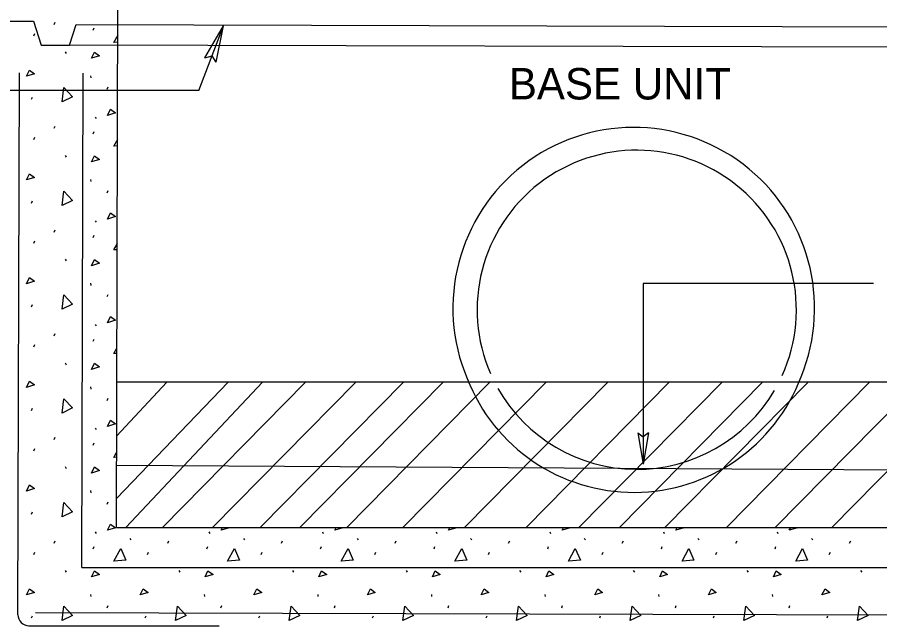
# Model space of a CAD drawing. Extents: x 4.74 to 11.91, y -5.26 to 4.54.
# Drawn here: x 6.154 to 7.798, y -1.238 to -0.077 of the extents above; entities that cross this region are included whole.
import ezdxf

# ---------------------------------------------------------------- set-up
doc = ezdxf.new("R2010")
doc.units = 0
for name, color, linetype in [('DETL-DIMS', 7, 'Continuous'), ('DETL-LINE', 7, 'Continuous'), ('DETL-NOTE', 7, 'Continuous'), ('DETL-PATT', 7, 'Continuous')]:
    doc.layers.add(name, color=color, linetype=linetype)

msp = doc.modelspace()

# ---------------------------------------------------------------- linework, layer by layer
at = {"layer": 'DETL-DIMS'}
for p, q in [((6.4998, -0.2168), (6.5467, -0.0933)), ((6.511, -0.1546), (6.5467, -0.0933)), ((6.5328, -0.1629), (6.5467, -0.0933)), ((6.511, -0.1546), (6.525, -0.1506)), ((6.5328, -0.1629), (6.525, -0.1506)), ((6.4998, -0.2168), (5.9955, -0.2168)), ((7.7863, -0.5848), (7.3468, -0.5848)), ((7.3468, -0.5848), (7.3468, -0.9299)), ((7.3368, -0.8699), (7.3468, -0.9299)), ((7.3368, -0.8699), (7.3468, -0.8774)), ((7.3568, -0.8699), (7.3468, -0.9299)), ((7.3568, -0.8699), (7.3468, -0.8774))]:
    msp.add_line(p, q, dxfattribs=at)
at = {"layer": 'DETL-LINE'}
for p, q in [((6.3425, -1.0502), (6.3468, 0.546)), ((6.1042, -0.0844), (6.1844, -0.0846)), ((6.1844, -0.0846), (6.1993, -0.1302)), ((6.253, -0.1303), (6.2659, -0.0908)), ((6.2659, -0.0908), (8.4204, -0.0965)), ((6.1993, -0.1302), (6.253, -0.1303)), ((6.253, -0.1293), (8.4421, -0.1351)), ((6.1549, -1.217), (6.1576, -0.1831)), ((6.2769, -1.1267), (6.2794, -0.1834)), ((8.3579, -0.7729), (6.3432, -0.7729)), ((6.3428, -0.9314), (8.3574, -0.9435)), ((6.3425, -1.0502), (8.3571, -1.0502)), ((6.2769, -1.1267), (8.425, -1.1267)), ((6.1881, -1.2125), (8.5207, -1.2187)), ((6.1757, -1.238), (6.5385, -1.238))]:
    msp.add_line(p, q, dxfattribs=at)
for centre, radius, start, end in [((7.329, -0.632), 0.3448, 337.6753, 202.9248), ((7.3347, -0.635), 0.3044, 335.6094, 203.5958), ((7.3291, -0.6425), 0.3409, 201.2948, 339.3052), ((7.3347, -0.635), 0.3044, 209.5167, 329.5671), ((6.1757, -1.2171), 0.0208, 179.7589, 270)]:
    msp.add_arc(centre, radius, start, end, dxfattribs=at)
at = {"layer": 'DETL-PATT'}
for p, q in [((6.2238, -0.0909), (6.226, -0.0866)), ((6.2984, -0.1014), (6.3, -0.0972)), ((6.1852, -0.1122), (6.1873, -0.1079)), ((6.2448, -0.1428), (6.2469, -0.146)), ((6.2931, -0.1884), (6.2936, -0.1927)), ((6.3251, -0.2142), (6.3267, -0.2099)), ((6.1809, -0.2335), (6.1825, -0.2292)), ((6.3022, -0.2673), (6.3038, -0.27)), ((6.2238, -0.2888), (6.226, -0.2845)), ((6.2984, -0.2994), (6.3, -0.2951)), ((6.1852, -0.3101), (6.1873, -0.3058)), ((6.2448, -0.3407), (6.2469, -0.3439)), ((6.2931, -0.3863), (6.2936, -0.3906)), ((6.3251, -0.4121), (6.3267, -0.4078)), ((6.1809, -0.4314), (6.1825, -0.4271)), ((6.3022, -0.4652), (6.3038, -0.4679)), ((6.2238, -0.4867), (6.226, -0.4824)), ((6.2984, -0.4973), (6.3, -0.493)), ((6.1852, -0.508), (6.1873, -0.5037)), ((6.2448, -0.5386), (6.2469, -0.5418)), ((6.2931, -0.5842), (6.2936, -0.5885)), ((6.3251, -0.61), (6.3267, -0.6057)), ((6.1809, -0.6293), (6.1825, -0.625)), ((6.3022, -0.6631), (6.3038, -0.6658)), ((6.2238, -0.6846), (6.226, -0.6803)), ((6.1852, -0.7059), (6.1873, -0.7016)), ((6.2984, -0.6952), (6.3, -0.6909)), ((6.2448, -0.7365), (6.2469, -0.7398)), ((6.3427, -0.995), (6.5556, -0.7729)), ((6.343, -0.8765), (6.4388, -0.7729)), ((6.3606, -1.0502), (6.621, -0.7729)), ((6.4303, -1.0502), (6.7033, -0.7729)), ((6.5258, -1.0502), (6.7988, -0.7729)), ((6.617, -1.0502), (6.8901, -0.7729)), ((6.6926, -1.0502), (6.9656, -0.7729)), ((6.7817, -1.0502), (7.0547, -0.7729)), ((6.8889, -1.0502), (7.162, -0.7729)), ((7.0066, -1.0502), (7.2797, -0.7729)), ((7.1237, -1.0502), (7.3968, -0.7729)), ((7.2243, -1.0502), (7.4974, -0.7729)), ((7.3017, -1.0502), (7.5747, -0.7729)), ((7.3885, -1.0502), (7.6615, -0.7729)), ((7.5056, -1.0502), (7.7787, -0.7729)), ((7.5988, -1.0502), (7.8718, -0.7729)), ((7.7064, -1.0502), (7.9795, -0.7729)), ((6.2931, -0.7822), (6.2936, -0.7864)), ((6.3251, -0.8079), (6.3267, -0.8036)), ((6.1809, -0.8272), (6.1825, -0.8229)), ((6.3022, -0.8611), (6.3038, -0.8637)), ((6.2238, -0.8825), (6.226, -0.8782)), ((6.1852, -0.9039), (6.1873, -0.8996)), ((6.2984, -0.8931), (6.3, -0.8888)), ((6.2448, -0.9344), (6.2469, -0.9377)), ((6.2931, -0.9801), (6.2936, -0.9844)), ((6.3251, -1.0058), (6.3267, -1.0015)), ((6.1809, -1.0252), (6.1825, -1.0209)), ((6.3022, -1.059), (6.3038, -1.0617)), ((6.5189, -1.059), (6.5205, -1.0617)), ((6.7355, -1.059), (6.7371, -1.0617)), ((6.9522, -1.059), (6.9538, -1.0617)), ((7.1689, -1.059), (7.1705, -1.0617)), ((7.3855, -1.059), (7.3871, -1.0617)), ((7.6022, -1.059), (7.6038, -1.0617)), ((6.2238, -1.0804), (6.226, -1.0762)), ((6.368, -1.0713), (6.3702, -1.074)), ((6.4405, -1.0804), (6.4426, -1.0762)), ((6.5847, -1.0713), (6.5868, -1.074)), ((6.6572, -1.0804), (6.6593, -1.0762)), ((6.8014, -1.0713), (6.8035, -1.074)), ((6.8738, -1.0804), (6.876, -1.0762)), ((7.018, -1.0713), (7.0202, -1.074)), ((7.0905, -1.0804), (7.0926, -1.0762)), ((7.2347, -1.0713), (7.2368, -1.074)), ((7.3072, -1.0804), (7.3093, -1.0762)), ((7.4514, -1.0713), (7.4535, -1.074)), ((7.5238, -1.0804), (7.526, -1.0762)), ((7.668, -1.0713), (7.6702, -1.074)), ((7.7405, -1.0804), (7.7426, -1.0762)), ((6.1852, -1.1018), (6.1873, -1.0975)), ((6.2984, -1.091), (6.3, -1.0867)), ((6.4018, -1.1018), (6.404, -1.0975)), ((6.5151, -1.091), (6.5167, -1.0867)), ((6.6185, -1.1018), (6.6207, -1.0975)), ((6.7318, -1.091), (6.7334, -1.0867)), ((6.8352, -1.1018), (6.8373, -1.0975)), ((6.9484, -1.091), (6.95, -1.0867)), ((7.0518, -1.1018), (7.054, -1.0975)), ((7.1651, -1.091), (7.1667, -1.0867)), ((7.2685, -1.1018), (7.2707, -1.0975)), ((7.3818, -1.091), (7.3834, -1.0867)), ((7.4852, -1.1018), (7.4873, -1.0975)), ((7.5984, -1.091), (7.6, -1.0867)), ((7.7018, -1.1018), (7.704, -1.0975)), ((6.2448, -1.1324), (6.2469, -1.1356)), ((6.4614, -1.1324), (6.4636, -1.1356)), ((6.6781, -1.1324), (6.6802, -1.1356)), ((6.8948, -1.1324), (6.8969, -1.1356)), ((7.1114, -1.1324), (7.1136, -1.1356)), ((7.3281, -1.1324), (7.3302, -1.1356)), ((7.5448, -1.1324), (7.5469, -1.1356)), ((7.7614, -1.1324), (7.7636, -1.1356)), ((6.2931, -1.178), (6.2936, -1.1823)), ((6.5097, -1.178), (6.5103, -1.1823)), ((6.7264, -1.178), (6.7269, -1.1823)), ((6.9431, -1.178), (6.9436, -1.1823)), ((7.1597, -1.178), (7.1603, -1.1823)), ((7.3764, -1.178), (7.3769, -1.1823)), ((7.5931, -1.178), (7.5936, -1.1823)), ((6.3251, -1.2038), (6.3267, -1.1995)), ((6.5418, -1.2038), (6.5434, -1.1995)), ((6.7584, -1.2038), (6.76, -1.1995)), ((6.9751, -1.2038), (6.9767, -1.1995)), ((7.1918, -1.2038), (7.1934, -1.1995)), ((7.4084, -1.2038), (7.41, -1.1995)), ((7.6251, -1.2038), (7.6267, -1.1995)), ((6.1809, -1.2231), (6.1825, -1.2188)), ((6.3975, -1.2231), (6.3992, -1.2188)), ((6.6142, -1.2231), (6.6158, -1.2188)), ((6.8309, -1.2231), (6.8325, -1.2188)), ((7.0475, -1.2231), (7.0492, -1.2188)), ((7.2642, -1.2231), (7.2658, -1.2188)), ((7.4809, -1.2231), (7.4825, -1.2188)), ((7.6975, -1.2231), (7.6992, -1.2188))]:
    msp.add_line(p, q, dxfattribs=at)
for points in [[(6.338, -0.1251), (6.3459, -0.1102)], [(6.3458, -0.1245), (6.338, -0.1251)], [(6.2952, -0.1551), (6.3006, -0.1433), (6.3102, -0.1503), (6.2952, -0.1551)], [(6.1712, -0.1895), (6.1771, -0.1777), (6.1862, -0.1846), (6.1712, -0.1895)], [(6.2389, -0.2383), (6.2426, -0.2109), (6.2592, -0.2287), (6.2389, -0.2383)], [(6.3256, -0.2641), (6.3315, -0.2523), (6.3412, -0.2593), (6.3256, -0.2641)], [(6.338, -0.323), (6.3452, -0.3095)], [(6.3451, -0.3225), (6.338, -0.323)], [(6.2952, -0.353), (6.3006, -0.3412), (6.3102, -0.3482), (6.2952, -0.353)], [(6.1712, -0.3874), (6.1771, -0.3756), (6.1862, -0.3826), (6.1712, -0.3874)], [(6.2389, -0.4362), (6.2426, -0.4089), (6.2592, -0.4266), (6.2389, -0.4362)], [(6.3256, -0.462), (6.3315, -0.4502), (6.3412, -0.4572), (6.3256, -0.462)], [(6.338, -0.5209), (6.3445, -0.5087)], [(6.3444, -0.5204), (6.338, -0.5209)], [(6.2952, -0.551), (6.3006, -0.5391), (6.3102, -0.5461), (6.2952, -0.551)], [(6.1712, -0.5853), (6.1771, -0.5735), (6.1862, -0.5805), (6.1712, -0.5853)], [(6.2389, -0.6342), (6.2426, -0.6068), (6.2592, -0.6245), (6.2389, -0.6342)], [(6.3256, -0.6599), (6.3315, -0.6481), (6.3412, -0.6551), (6.3256, -0.6599)], [(6.338, -0.7188), (6.3437, -0.708)], [(6.3437, -0.7184), (6.338, -0.7188)], [(6.2952, -0.7489), (6.3006, -0.7371), (6.3102, -0.744), (6.2952, -0.7489)], [(6.1712, -0.7832), (6.1771, -0.7714), (6.1862, -0.7784), (6.1712, -0.7832)], [(6.2389, -0.8321), (6.2426, -0.8047), (6.2592, -0.8224), (6.2389, -0.8321)], [(6.3256, -0.8578), (6.3315, -0.846), (6.3412, -0.853), (6.3256, -0.8578)], [(6.338, -0.9167), (6.343, -0.9073)], [(6.343, -0.9164), (6.338, -0.9167)], [(6.2952, -0.9468), (6.3006, -0.935), (6.3102, -0.942), (6.2952, -0.9468)], [(6.1712, -0.9811), (6.1771, -0.9693), (6.1862, -0.9763), (6.1712, -0.9811)], [(6.2389, -1.03), (6.2426, -1.0026), (6.2592, -1.0203), (6.2389, -1.03)], [(6.3256, -1.0558), (6.3315, -1.0439), (6.3412, -1.0509), (6.3256, -1.0558)], [(6.5423, -1.0558), (6.5451, -1.0502)], [(6.5569, -1.0502), (6.5579, -1.0509), (6.5423, -1.0558)], [(6.759, -1.0558), (6.7617, -1.0502)], [(6.7735, -1.0502), (6.7745, -1.0509), (6.759, -1.0558)], [(6.9756, -1.0558), (6.9784, -1.0502)], [(6.9902, -1.0502), (6.9912, -1.0509), (6.9756, -1.0558)], [(7.1923, -1.0558), (7.1951, -1.0502)], [(7.2069, -1.0502), (7.2079, -1.0509), (7.1923, -1.0558)], [(7.409, -1.0558), (7.4117, -1.0502)], [(7.4235, -1.0502), (7.4245, -1.0509), (7.409, -1.0558)], [(7.6256, -1.0558), (7.6284, -1.0502)], [(7.6402, -1.0502), (7.6412, -1.0509), (7.6256, -1.0558)], [(6.338, -1.1146), (6.3509, -1.0905), (6.3605, -1.113), (6.338, -1.1146)], [(6.5546, -1.1146), (6.5675, -1.0905), (6.5772, -1.113), (6.5546, -1.1146)], [(6.7713, -1.1146), (6.7842, -1.0905), (6.7938, -1.113), (6.7713, -1.1146)], [(6.988, -1.1146), (7.0009, -1.0905), (7.0105, -1.113), (6.988, -1.1146)], [(7.2046, -1.1146), (7.2175, -1.0905), (7.2272, -1.113), (7.2046, -1.1146)], [(7.4213, -1.1146), (7.4342, -1.0905), (7.4438, -1.113), (7.4213, -1.1146)], [(7.638, -1.1146), (7.6509, -1.0905), (7.6605, -1.113), (7.638, -1.1146)], [(6.2952, -1.1447), (6.3006, -1.1329), (6.3102, -1.1399), (6.2952, -1.1447)], [(6.5119, -1.1447), (6.5172, -1.1329), (6.5269, -1.1399), (6.5119, -1.1447)], [(6.7285, -1.1447), (6.7339, -1.1329), (6.7436, -1.1399), (6.7285, -1.1447)], [(6.9452, -1.1447), (6.9506, -1.1329), (6.9602, -1.1399), (6.9452, -1.1447)], [(7.1619, -1.1447), (7.1672, -1.1329), (7.1769, -1.1399), (7.1619, -1.1447)], [(7.3785, -1.1447), (7.3839, -1.1329), (7.3936, -1.1399), (7.3785, -1.1447)], [(7.5952, -1.1447), (7.6006, -1.1329), (7.6102, -1.1399), (7.5952, -1.1447)], [(6.1712, -1.1791), (6.1771, -1.1673), (6.1862, -1.1742), (6.1712, -1.1791)], [(6.3879, -1.1791), (6.3938, -1.1673), (6.4029, -1.1742), (6.3879, -1.1791)], [(6.6046, -1.1791), (6.6105, -1.1673), (6.6196, -1.1742), (6.6046, -1.1791)], [(6.8212, -1.1791), (6.8271, -1.1673), (6.8362, -1.1742), (6.8212, -1.1791)], [(7.0379, -1.1791), (7.0438, -1.1673), (7.0529, -1.1742), (7.0379, -1.1791)], [(7.2546, -1.1791), (7.2605, -1.1673), (7.2696, -1.1742), (7.2546, -1.1791)], [(7.4712, -1.1791), (7.4771, -1.1673), (7.4862, -1.1742), (7.4712, -1.1791)], [(7.6879, -1.1791), (7.6938, -1.1673), (7.7029, -1.1742), (7.6879, -1.1791)], [(6.2389, -1.2279), (6.2426, -1.2005), (6.2592, -1.2182), (6.2389, -1.2279)], [(6.4555, -1.2279), (6.4593, -1.2005), (6.4759, -1.2182), (6.4555, -1.2279)], [(6.6722, -1.2279), (6.6759, -1.2005), (6.6926, -1.2182), (6.6722, -1.2279)], [(6.8889, -1.2279), (6.8926, -1.2005), (6.9092, -1.2182), (6.8889, -1.2279)], [(7.1055, -1.2279), (7.1093, -1.2005), (7.1259, -1.2182), (7.1055, -1.2279)], [(7.3222, -1.2279), (7.3259, -1.2005), (7.3426, -1.2182), (7.3222, -1.2279)], [(7.5389, -1.2279), (7.5426, -1.2005), (7.5592, -1.2182), (7.5389, -1.2279)], [(7.7555, -1.2279), (7.7593, -1.2005), (7.7759, -1.2182), (7.7555, -1.2279)]]:
    msp.add_lwpolyline(points, dxfattribs=at)

# ---------------------------------------------------------------- texts
at = {"layer": 'DETL-NOTE'}
msp.add_text('BASE UNIT', height=0.06, dxfattribs=at).set_placement((7.0908, -0.2338))

doc.saveas('drawing.dxf')
